// Mitsubishi GX Works2 project: 29.6个点动+1自锁(逻辑指令)   PLC: FX3U/FX3UC

PROGRAM MAIN
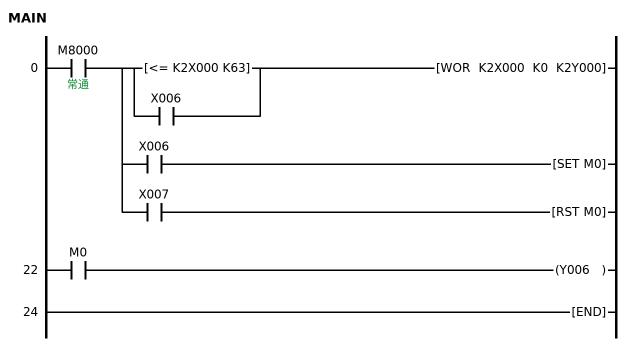
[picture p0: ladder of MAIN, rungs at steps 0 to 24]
0     LD      M8000  ; 常通
      MPS
      LD<=    K2X000 K63
      OR      X006
      ANB
      WOR     K2X000 K0 K2Y000
        [note] 点动控制
      MRD
      AND     X006
      SET     M0
        [note] 自锁控制
      MPP
      AND     X007
      RST     M0
22    LD      M0
      OUT     Y006
24    END
END_PROGRAM
